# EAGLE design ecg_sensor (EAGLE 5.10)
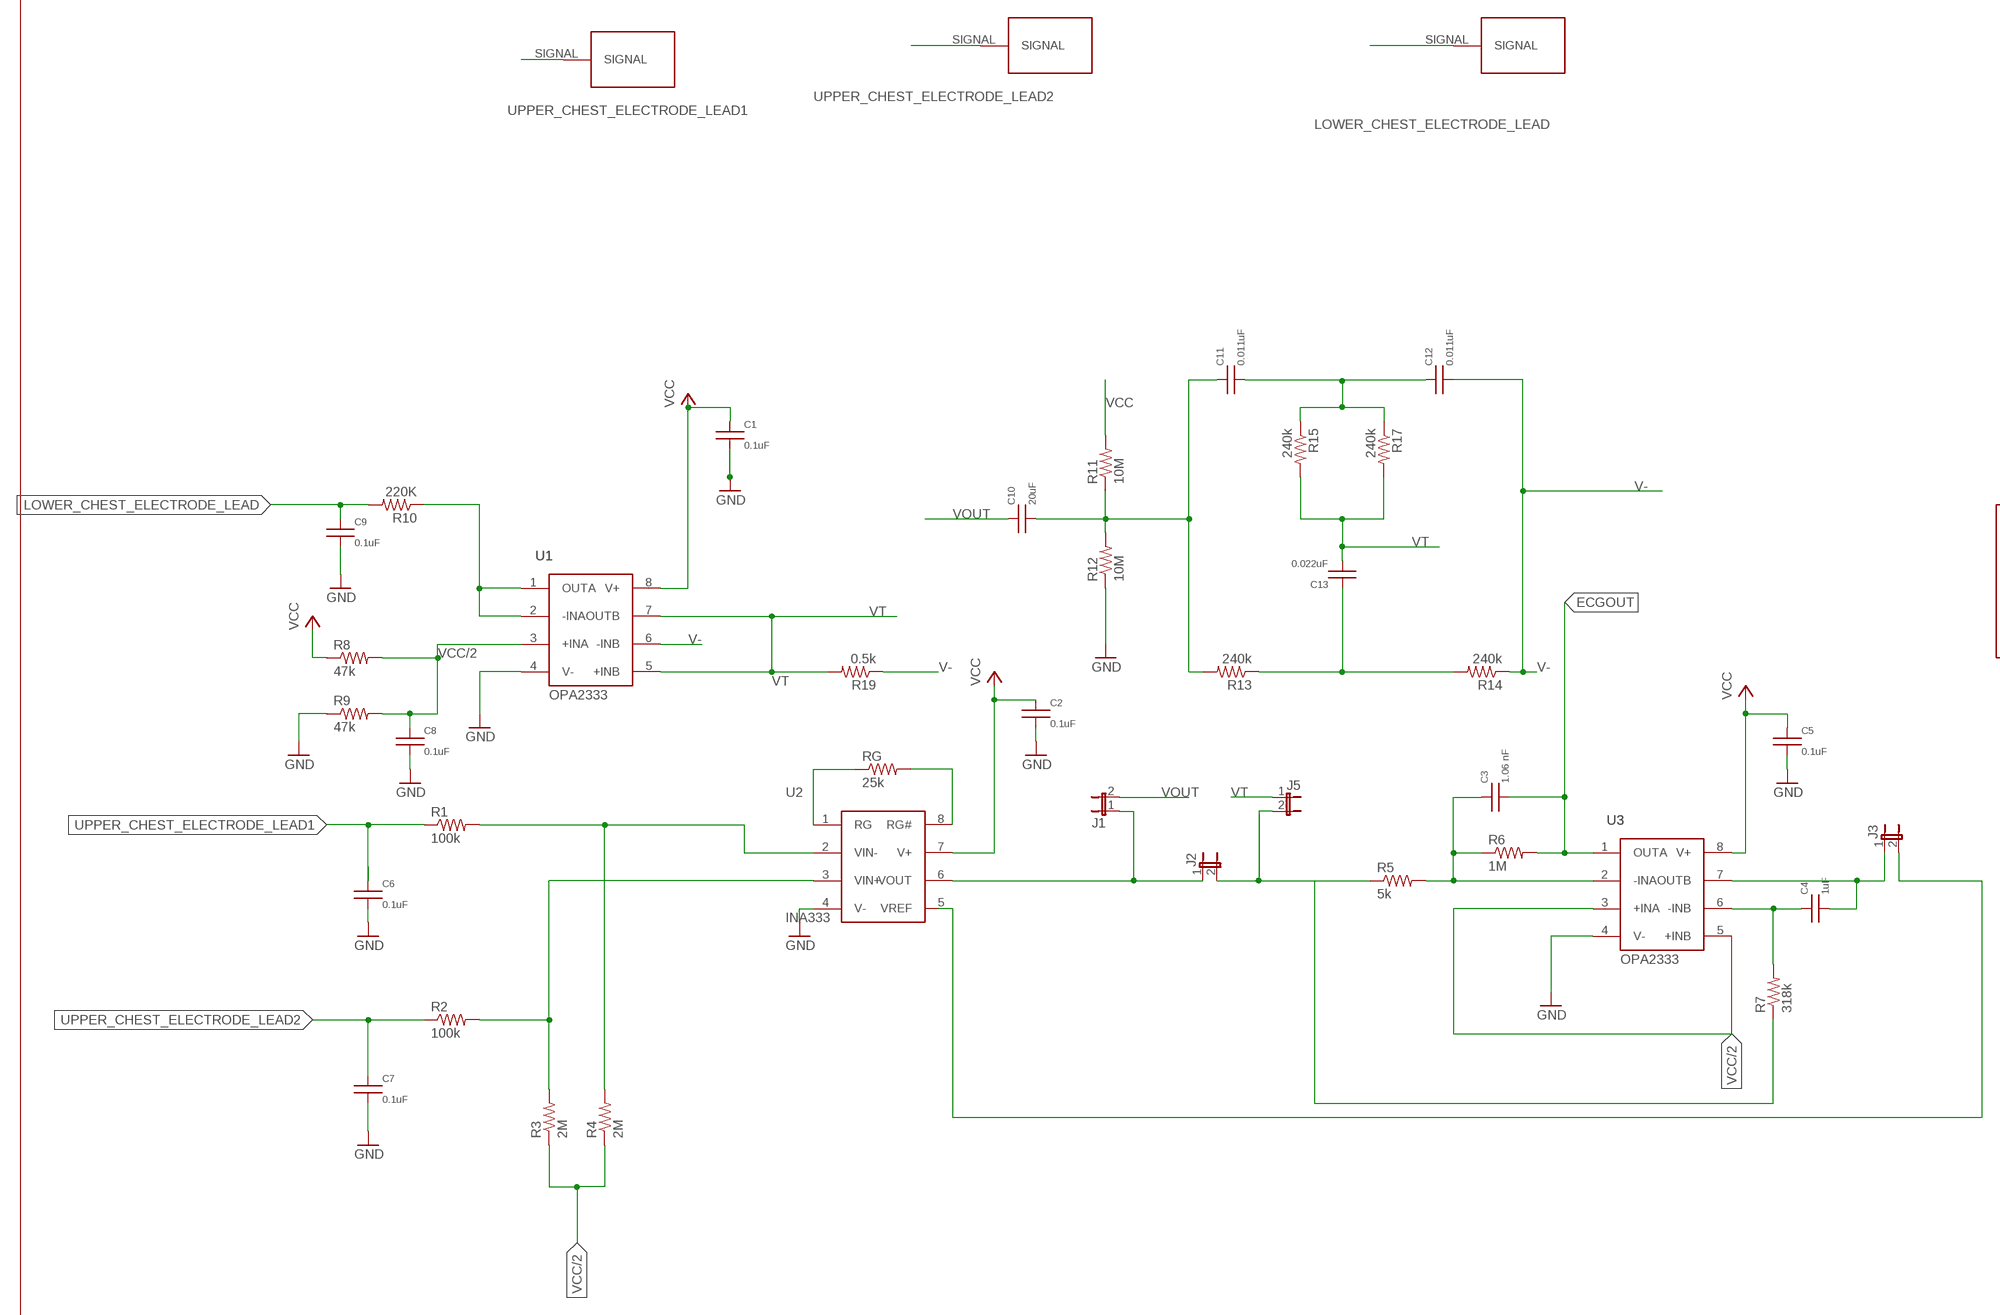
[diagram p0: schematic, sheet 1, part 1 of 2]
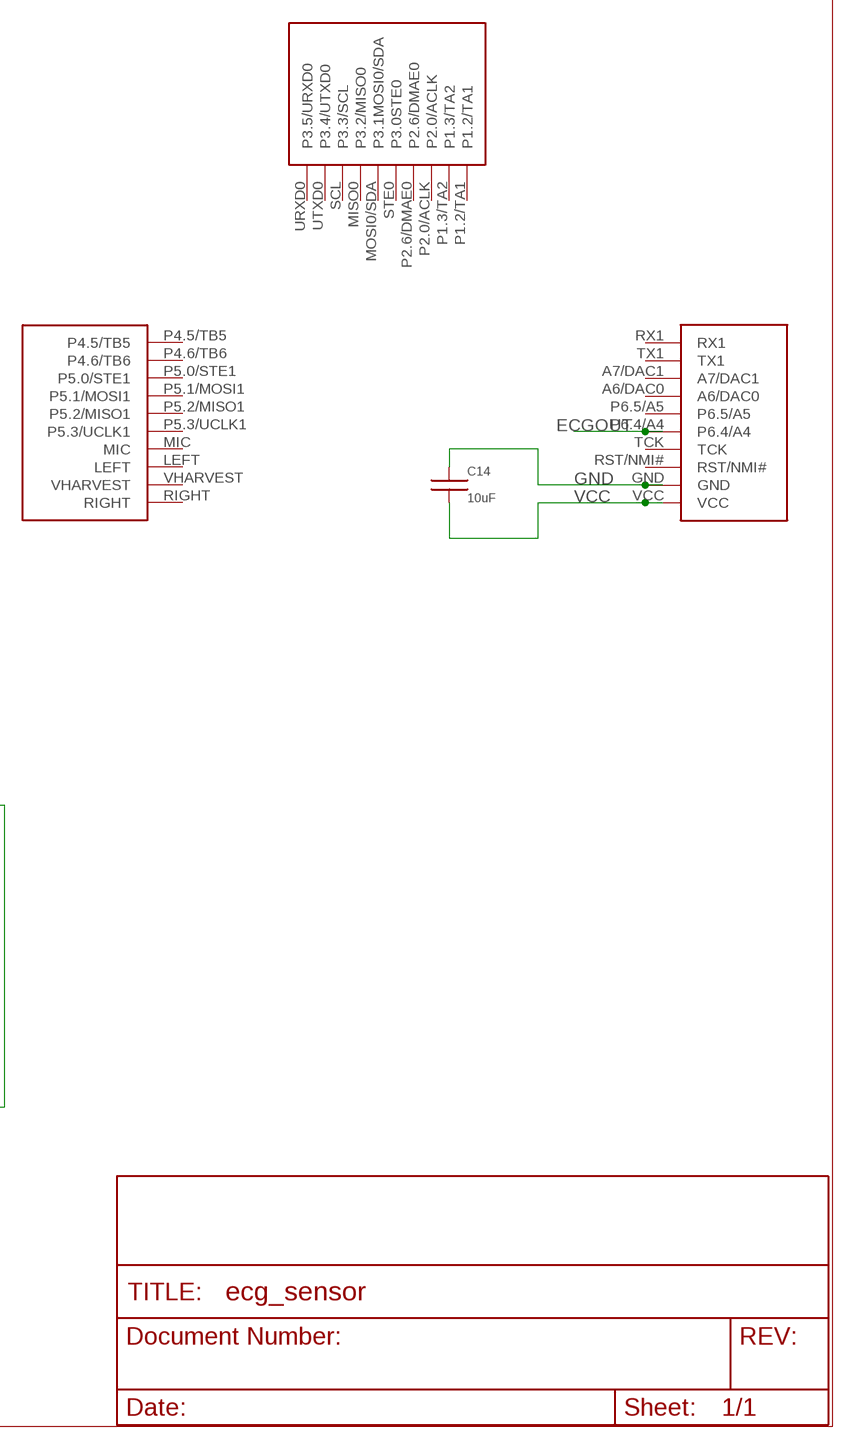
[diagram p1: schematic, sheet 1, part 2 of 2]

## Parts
BLACK  PLASTICJACKNEW  [PLASTICJACKNEW]
C1  0.1uF  C0603  [C0603]
C2  0.1uF  C0603  [C0603]
C3  1.06 nF  C0603  [C0603]
C4  1uF  C0603  [C0603]
C5  0.1uF  C0603  [C0603]
C6  0.1uF  C0603  [C0603]
C7  0.1uF  C0603  [C0603]
C8  0.1uF  C0603  [C0603]
C9  0.1uF  C0603  [C0603]
C10  20uF  C0603  [C0603]
C11  0.011uF  C1206  [C1206]
C12  0.011uF  C1206  [C1206]
C13  0.022uF  C1206  [C1206]
C14  10uF  C0603  [C0603]
J1  JUMPER-2PTH  [1X02]
J2  JUMPER-2PTH  [1X02]
J3  JUMPER-2PTH  [1X02]
J4  HIJACK-INTERFACE  [HIJACK-INTERFACE-30PIN]
J5  JUMPER-2PTH  [1X02]
R1  100k  R-US_R0603  [R0603]
R2  100k  R-US_R0603  [R0603]
R3  2M  R-US_R0603  [R0603]
R4  2M  R-US_R0603  [R0603]
R5  5k  R-US_R0603  [R0603]
R6  1M  R-US_R0603  [R0603]
R7  318k  R-US_R0603  [R0603]
R8  47k  R-US_R0603  [R0603]
R9  47k  R-US_R0603  [R0603]
R10  220K  R-US_R0603  [R0603]
R11  10M  R-US_R0603  [R0603]
R12  10M  R-US_R0603  [R0603]
R13  240k  R-US_R0603  [R0603]
R14  240k  R-US_R0603  [R0603]
R15  240k  R-US_R0603  [R0603]
R17  240k  R-US_R0603  [R0603]
R19  0.5k  R-US_R0603  [R0603]
RED  PLASTICJACKNEW  [PLASTICJACKNEW]
RG  25k  R-US_R0603  [R0603]
U1  OPA2333  [SOIC]
U2  INA333  [MSOP8]
U3  OPA2333  [SOIC]
WHITE  PLASTICJACKNEW  [PLASTICJACKNEW]

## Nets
ECGOUT: C3.2 J4.P6.4/A4 R6.2 U3.1(OUTA)
GND: C1.2 C2.2 C5.2 C6.2 C7.2 C8.2 C9.2 C14.1 J4.GND R9.1 R12.1 U1.4(V-) U2.4(V-) U3.4(V-)
LOWER_CHEST_ELECTRODE_LEAD: BLACK.SIGNAL C9.1 R10.2
N$1: J1.1 J2.1 U2.6(VOUT)
N$2: R10.1 U1.1(OUTA) U1.2(-INA)
N$3: C4.2 J3.1 U3.7(OUTB)
N$4: RG.1 U2.1(RG)
N$5: RG.2 U2.8(RG#)
N$6: R1.2 R4.2 U2.2(VIN-)
N$7: C11.2 C12.1 R15.1 R17.1
N$8: R2.2 R3.2 U2.3(VIN+)
N$10: C10.2 C11.1 R11.1 R12.2 R13.2
N$11: J2.2 J5.2 R5.1 R7.1
N$12: C13.1 R13.1 R14.2
N$13: C3.1 R5.2 R6.1 U3.2(-INA)
N$17: C4.1 R7.2 U3.6(-INB)
UPPER_CHEST_ELECTRODE_LEAD1: C6.1 R1.1 RED.SIGNAL
UPPER_CHEST_ELECTRODE_LEAD2: C7.1 R2.1 WHITE.SIGNAL
V-: C12.2 R14.1 R19.1 U1.6(-INB)
VCC: C1.1 C2.1 C5.1 C14.2 J4.VCC R8.1 R11.2 U1.8(V+) U2.7(V+) U3.8(V+)
VCC/2: C8.1 R3.1 R4.1 R8.2 R9.2 U1.3(+INA) U3.3(+INA) U3.5(+INB)
VOUT: C10.1 J1.2
VREF: J3.2 U2.5(VREF)
VT: C13.2 J5.1 R15.2 R17.2 R19.2 U1.5(+INB) U1.7(OUTB)
Unconnected: J4.A6/DAC0 J4.A7/DAC1 J4.LEFT J4.MIC J4.MISO0(P3.2/MISO0) J4.MOSI0/SDA(P3.1MOSI0/SDA) J4.P1.2/TA1 J4.P1.3/TA2 J4.P2.0/ACLK J4.P2.6/DMAE0 J4.P4.5/TB5 J4.P4.6/TB6 J4.P5.0/STE1 J4.P5.1/MOSI1 J4.P5.2/MISO1 J4.P5.3/UCLK1 J4.P6.5/A5 J4.RIGHT J4.RST/NMI# J4.RX1 J4.SCL(P3.3/SCL) J4.STE0(P3.0STE0) J4.TCK J4.TX1 J4.URXD0(P3.5/URXD0) J4.UTXD0(P3.4/UTXD0) J4.VHARVEST

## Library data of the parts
BLACK RED WHITE = sonal:PLASTICJACKNEW
C1-C14 = umich:C
J1-J3 J5 = umich:JUMPER-2: Jumper
J4 = umich:HIJACK-INTERFACE
R1-R15 R17 R19 RG = rcl:R-US_: RESISTOR, American symbol
U1 U3 = sonal:OPA2333
U2 = sonal:INA333

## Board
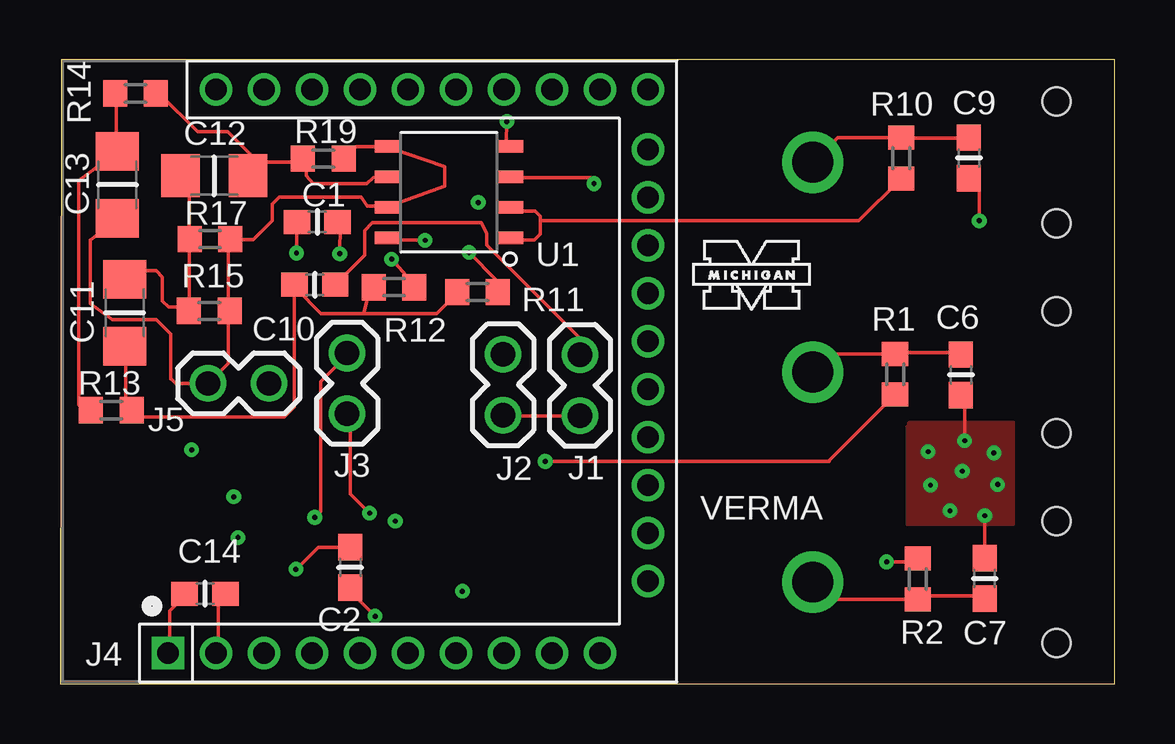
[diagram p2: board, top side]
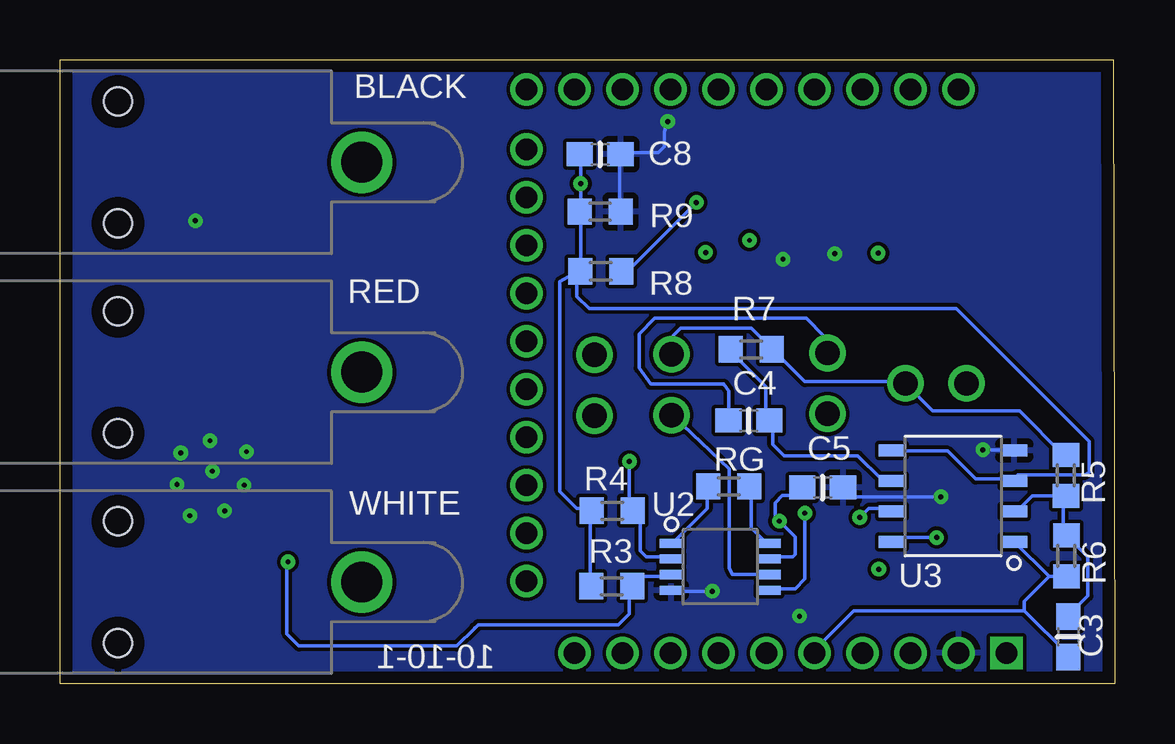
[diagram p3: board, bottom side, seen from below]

Size 43.94 x 26.01 mm. Coordinates in mm from the lower left corner, seen from the top.
Outline: 0,0 43.94,0 43.94,26.01 0.05,26.01 0,0
Copper layers (1+2*15+16): Top 0.0178mm / dielectric 0.3048mm / $GND 0.0356mm / dielectric 0.7112mm / $VCC 0.0356mm / dielectric 0.3048mm / Bottom 0.0178mm
Design rules "SSC-EAGLE-4Lyr_v1.0.0.3": minimum track width 6mil, minimum drill 8mil, track to track 6mil, track to pad 6mil, pad to pad 6mil, via to via 6mil, smd to smd 6mil, copper to edge 20mil, drill to drill 16mil, minimum pad ring 8mil, minimum via ring 8mil, stop-mask expansion 3mil, vias tented up to drill 0mil, thermal gap 10mil

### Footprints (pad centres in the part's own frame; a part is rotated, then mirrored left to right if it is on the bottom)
PLASTICJACKNEW = drill 1.702 pad 2.54 round: SIGNAL -7.874,0 | hole 1.168: 2.286,2.54; 2.286,-2.54
C0603 = smd 1.1 x 1: 1 -0.85,0; 2 0.85,0
C1206 = smd 1.6 x 1.8: 1 -1.4,0; 2 1.4,0
1X02 = drill 1.016 round: 1 0,0; 2 2.54,0
HIJACK-INTERFACE-30PIN = drill 0.89 pad 1.346 round: A6/DAC0 2.89,-12.46; A7/DAC1 4.89,-12.46; GND -7.11,-12.46; LEFT -3.11,11.04; MIC -1.11,11.04; MISO0 10.89,2.54; MOSI0/SDA 10.89,0.54; P1.2/TA1 10.89,-9.46; P1.3/TA2 10.89,-7.46; P2.0/ACLK 10.89,-5.46; P2.6/DMAE0 10.89,-3.46; P4.5/TB5 10.89,11.04; P4.6/TB6 8.89,11.04; P5.0/STE1 6.89,11.04; P5.1/MOSI1 4.89,11.04; P5.2/MISO1 2.89,11.04; P5.3/UCLK1 0.89,11.04; P6.4/A4 -1.11,-12.46; P6.5/A5 0.89,-12.46; RIGHT -7.11,11.04; RST/NMI# -5.11,-12.46; RX1 8.89,-12.46; SCL 10.89,4.54; STE0 10.89,-1.46; TCK -3.11,-12.46; TX1 6.89,-12.46; URXD0 10.89,8.54; UTXD0 10.89,6.54; VHARVEST -5.11,11.04 | drill 0.89 pad 1.346 square: VCC -9.11,-12.46
R0603 = smd 1 x 1.1: 1 -0.85,0; 2 0.85,0
SOIC = smd 0.51 x 1.1: 1 -1.905,-2.55; 2 -0.635,-2.55; 3 0.635,-2.55; 4 1.905,-2.55; 5 1.905,2.55; 6 0.635,2.55; 7 -0.635,2.55; 8 -1.905,2.55
MSOP8 = smd 0.38 x 0.975: 1 -0.975,-2.038; 2 -0.325,-2.038; 3 0.325,-2.038; 4 0.975,-2.038; 5 0.975,2.038; 6 0.325,2.038; 7 -0.325,2.038; 8 -0.975,2.038

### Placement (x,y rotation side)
BLACK  39.24,21.74 180 bottom
C1  10.72,19.25 0 top
C2  12.09,4.85 270 top
C3  1.93,1.96 270 bottom
C4  15.24,10.97 180 bottom
C5  12.17,8.18 0 bottom
C6  37.54,12.88 270 top
C7  38.53,4.39 90 top
C8  21.44,22.07 0 bottom
C9  37.87,21.92 270 top
C10  10.62,16.64 180 top
C11  2.69,15.47 90 top
C12  6.43,21.18 0 top
C13  2.39,20.8 270 top
C14  6.05,3.76 180 top
J1  21.67,11.18 90 top
J2  18.47,11.2 90 top
J3  11.96,13.79 270 top
J4  13.61,13.74 0 top
J5  6.17,12.52 0 top
R1  34.8,12.9 270 top
R2  35.74,4.37 90 top
R3  20.95,4.06 0 bottom
R4  20.93,7.21 0 bottom
R5  2.03,8.69 270 bottom
R6  2.01,5.33 270 bottom
R7  15.14,13.94 180 bottom
R8  21.41,17.2 180 bottom
R9  21.44,19.69 180 bottom
R10  35.05,21.92 90 top
R11  17.4,16.33 0 top
R12  13.92,16.54 180 top
R13  2.13,11.4 0 top
R14  3.15,24.61 180 top
R15  6.22,15.54 0 top
R17  6.25,18.54 0 top
R19  10.97,21.89 0 top
RED  39.24,12.99 180 bottom
RG  16.08,8.23 0 bottom
U1  16.21,20.5 90 top
U2  16.43,4.88 270 bottom
U3  6.73,7.82 90 bottom
U$1  [UMICH]  26.29,15.39 0 top
WHITE  39.24,4.24 180 bottom

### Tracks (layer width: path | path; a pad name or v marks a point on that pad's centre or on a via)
ECGOUT
  Bottom 0.152: 3.76,3.05 1.93,1.22 C3.2 | 4.17,5.89 U3.1 2.73,4.47 | R6.2 2.13,4.47 2.73,4.47 | 3.76,3.05 10.87,3.05 12.5,1.42 J4.P6.4/A4 | 2.73,4.47 3.76,3.44 3.76,3.05
GND  (via drill 0.2)
  Top 0.152: C6.2 37.69,11.99 v37.69,10.13 | 38.51,5.28 C7.2 v38.53,7.01 | C9.2 37.9,20.93 38.3,20.52 v38.3,19.3 | J4.GND 6.6,1.42 6.6,3.45 6.81,3.66 C14.1 7.01,3.86 | C2.2 12.09,3.86 v13.13,2.82 | v13.82,17.7 14.73,16.66 R12.1 | v11.66,17.93 11.68,19.1 C1.2 | v18.62,23.44 18.59,22.56 U1.4
  Bottom 0.152: v16.76,3.86 18.39,3.86 U2.4 | C5.2 11.28,8.13 11.3,7.8 v7.24,7.8 | R9.1 20.63,19.71 20.63,21.95 C8.2 20.42,22.15 19.01,22.15 U1.4 18.76,23 v18.62,23.44 | v5.49,9.75 4.17,9.75 U3.4
  other vias: 36.17,9.68 37.59,8.86 38.91,9.63 39.07,8.31 36.27,8.28 37.08,7.21
  pour Bottom: 0.33,25.86 43.71,25.86 43.61,0.15 0.36,0.25 0.28,25.98
  pour Top: 35.41,10.9 39.73,10.9 39.73,6.65 35.31,6.65 35.31,10.72 35.36,10.72 35.36,10.87
LOWER_CHEST_ELECTRODE_LEAD
  Top 0.152: C9.1 37.69,22.76 R10.2 32.4,22.77 BLACK.SIGNAL
N$1
  Top 0.152: J1.1 18.59,11.18 J2.1
  Bottom 0.152: 14.53,4.67 U2.6 14.42,4.57 15.93,4.57 16.05,4.83 16.05,8.97 18.39,11.18 J2.1
N$2
  Top 0.152: 18.8,18.69 U1.1 18.86,18.49 19.76,18.49 20.02,18.75 20.02,19.3 | U1.2 18.8,19.71 19.81,19.71 20.02,19.51 20.02,19.3 | 35.05,20.93 R10.1 33.29,19.3 20.02,19.3
N$3  (via drill 0.2)
  Top 0.152: J3.1 11.89,13.61 10.87,12.6 10.87,7.19 v10.62,6.93
  Bottom 0.152: U3.7 9.45,7.32 10.24,7.32 v10.62,6.93 | J3.1 12.09,13.82 12.09,14.48 12.85,15.24 19.15,15.24 19.81,14.58 19.81,13.16 19.33,12.5 16.28,12.5 16.08,12.22 C4.2
N$4
  Bottom 0.152: U2.1 18.39,5.89 16.97,7.32 16.97,8.13 RG.1
N$5
  Bottom 0.152: U2.8 14.53,5.89 15.14,6.5 15.14,8.13 RG.2
N$6  (via drill 0.2)
  Top 0.152: 34.47,11.99 34.65,11.99 R1.2 32.06,9.31 32.06,9.27 v20.22,9.27
  Bottom 0.152: U2.2 18.59,5.28 19.51,5.28 19.76,5.54 19.76,6.9 R4.2 | R4.2 20.02,7.11 | v20.22,9.27 20.22,7.32 R4.2
N$7
  Top 0.152: C11.2 2.74,16.87 2.9,16.87 3.25,17.22 4.01,17.22 4.27,16.97 4.27,15.95 4.52,15.7 5.22,15.7 R15.1 5.39,15.65 5.39,18.49 R17.1 5.39,18.69 5.39,20.93 5.18,21.13 C12.1
N$8  (via drill 0.2)
  Top 0.152: v34.44,5.08 35.66,5.08 R2.2
  Bottom 0.152: U2.3 18.59,4.47 20.02,4.47 20.02,4.06 R3.2 20.22,4.06 20.22,2.92 20.68,2.46 26.52,2.46 26.67,2.31 | v34.44,5.08 34.49,5.03 34.49,2.08 33.99,1.58 27.41,1.58 26.67,2.31 | 26.67,2.31 26.67,2.34
N$10
  Top 0.152: C11.1 2.74,14.02 2.74,11.79 2.95,11.58 R13.2 3.15,11.38 3.4,11.13 9.35,11.13 9.77,11.55 C10.2 9.86,16.46 10.87,15.44 12.65,15.44 | R12.2 12.9,16.46 12.65,15.44 | 16.36,16.26 R11.1 16.55,16.3 15.7,15.44 12.65,15.44
N$11
  Bottom 0.152: R5.1 2.13,9.55 3.96,11.38 7.57,11.38 J5.2 | J5.2 8.64,12.4 | J5.2 8.84,12.6 12.9,12.6 14.12,13.82 R7.1 14.33,14.02 15.14,14.83 18.09,14.83 18.39,14.53 18.39,13.82 J2.2
N$12
  Top 0.152: R13.1 0.79,11.63 0.79,20.98 2.34,22.15 C13.1 2.34,22.35 2.34,24.59 R14.2
N$13
  Bottom 0.152: C3.1 1.93,2.85 1.12,3.66 1.12,5.28 1.93,6.1 R6.1 2.13,6.3 2.13,7.72 R5.2 3.44,7.84 4.17,7.11 U3.2
N$17
  Bottom 0.152: U3.6 9.45,8.53 9.73,8.53 10.69,9.5 13.77,9.5 14.25,9.98 14.25,10.83 C4.1 | C4.1 14.33,10.97 | R7.2 15.95,13.82 14.53,12.4 14.53,10.97 C4.1
UPPER_CHEST_ELECTRODE_LEAD1
  Top 0.152: R1.1 34.85,13.82 37.49,13.82 C6.1 | R1.1 34.65,13.61 | RED.SIGNAL 32.13,13.75 R1.1
UPPER_CHEST_ELECTRODE_LEAD2
  Top 0.152: R2.1 35.87,3.66 38.51,3.66 C7.1 | R2.1 35.66,3.66 | WHITE.SIGNAL 32.09,3.52 R2.1
V-
  Top 0.152: 8.03,21.74 10.06,21.74 R19.1 10.26,21.74 10.26,21.18 10.54,20.88 10.57,20.85 12.78,20.85 13.06,21.11 U1.6 | 8.03,21.74 8.03,21.34 C12.2 7.82,21.34 7.42,21.34 | R14.1 4.17,24.59 5.74,23.01 6.99,23.01 8.03,21.97 8.03,21.74
VCC  (via drill 0.2)
  Top 0.152: 18.19,16.46 R11.2 18.19,16.26 18.19,16.84 v17.04,17.98 | U1.8 13.72,18.49 v15.21,18.49 | J4.VCC 4.57,1.42 4.57,3.05 5.18,3.66 C14.2 5.39,3.86 | v9.86,17.96 9.86,19.1 C1.1 | 12.5,5.89 12.09,5.89 C2.1 10.77,5.69 9.86,4.8 v9.83,4.78
  Bottom 0.152: U2.7 14.33,5.28 13.41,5.28 13.31,5.39 13.31,6.12 v13.97,6.78 14.15,6.78 14.15,7.54 13.84,7.85 12.9,7.85 12.9,8.13 C5.1 13.11,8.13 | U3.8 9.45,6.1 v7.42,6.1 | R8.1 20.42,17.07 v17.42,20.07
VCC/2  (via drill 0.2)
  Top 0.152: U1.3 18.78,21.11 22.12,21.11 v22.25,20.85
  Bottom 0.152: 9.25,9.75 U3.5 9.26,9.7 6.96,9.7 5.79,8.53 4.37,8.53 U3.3 4.17,8.53 4.04,8.71 1.24,8.71 1.07,8.84 1.07,10.11 6.6,15.65 21.9,15.65 22.4,16.15 22.4,17.06 R8.2 | R3.1 21.84,4.06 21.84,7.11 R4.1 21.84,7.32 22.4,7.32 23.11,8.03 23.11,16.76 22.61,17.07 22.45,17.07 R8.2 | R8.2 22.25,17.27 22.25,19.51 R9.2 22.25,19.71 v22.25,20.85 | C8.1 22.25,21.95 v22.25,20.85 | v22.25,20.85 22.25,20.93
VOUT
  Top 0.152: C10.1 11.48,16.66 12.7,17.88 12.7,18.9 13.01,19.23 17.55,19.23 17.78,18.77 17.78,18.29 21.64,14.43 21.64,13.61 J1.2
VREF  (via drill 0.2)
  Top 0.152: v12.9,7.11 12.09,7.93 12.09,11.18 J3.2
  Bottom 0.152: v12.9,7.11 12.9,4.37 13.31,3.96 14.34,3.96 U2.5
VT
  Top 0.152: U1.5 13.72,22.35 16.03,21.56 16.03,20.75 13.72,19.91 U1.7 13.51,19.91 12.8,19.91 12.55,20.29 9.14,20.29 8.84,19.99 8.84,19.3 8.05,18.52 7.59,18.52 R17.2 7.01,18.49 7.01,15.65 R15.2 7.01,15.44 7.01,13.36 J5.1 | R19.2 11.89,21.95 12.34,22.4 U1.5 | U1.5 13.51,22.35 | C13.2 2.34,19.3 1.27,18.49 1.27,15.85 2.18,15.19 4.01,15.19 4.62,14.58 4.62,12.73 | J5.1 5.99,12.6 | 4.62,12.73 4.62,12.7 | 4.62,12.73 4.83,12.52 J5.1

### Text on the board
tPlace: VERMA
bNames: 10-10-1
